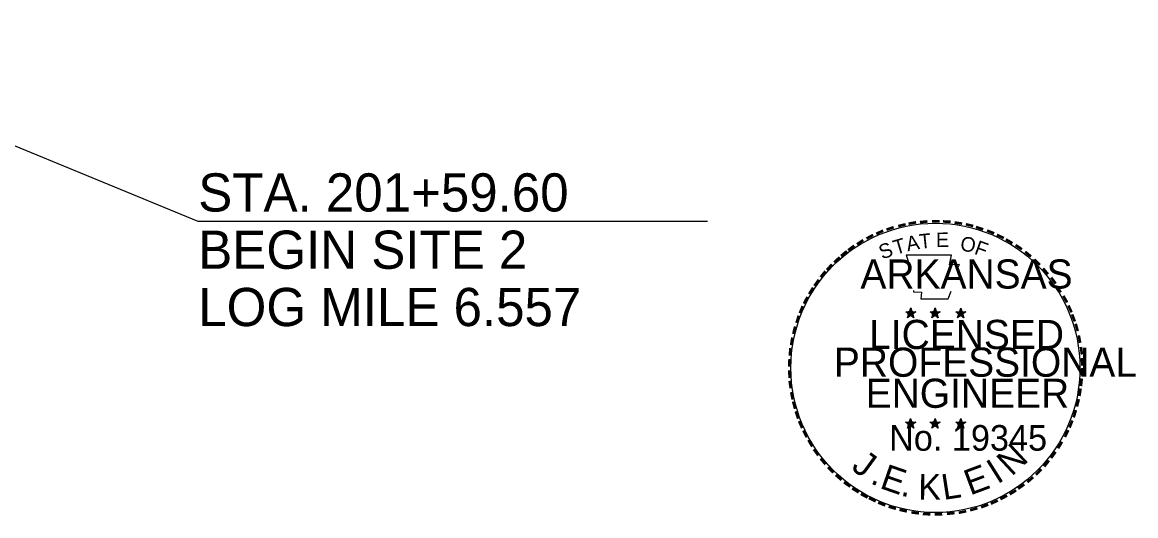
# Model space of a CAD drawing. Extents: x 1334737.7 to 1334827.2, y 402732.3 to 402753.5.
# Drawn here: x 1334760.94 to 1334768.64, y 402733.45 to 402736.86 of the extents above; entities that cross this region are included whole.
import ezdxf

# ---------------------------------------------------------------- set-up
doc = ezdxf.new("R2010")
doc.units = 0
doc.layers.add('Default', color=7, linetype='Continuous')
doc.layers.add('S_BASELINE_ANNOT', color=7, linetype='Continuous')

msp = doc.modelspace()

# ---------------------------------------------------------------- linework, layer by layer
at = {"layer": 'Default'}
for p, q in [((1334762.1527, 402735.4822), (1334753.3271, 402739.1037)), ((1334765.6746, 402735.4822), (1334762.1527, 402735.4822))]:
    msp.add_line(p, q, dxfattribs=at)
at = {"layer": 'S_BASELINE_ANNOT'}
for p, q in [((1334767.0814, 402734.8838), (1334767.0773, 402734.8578)), ((1334767.0814, 402734.8464), (1334767.0814, 402734.8838)), ((1334767.0814, 402734.8838), (1334767.0866, 402734.8589)), ((1334767.2504, 402734.8838), (1334767.2463, 402734.8578)), ((1334767.2504, 402734.8464), (1334767.2504, 402734.8838)), ((1334767.2504, 402734.8838), (1334767.2546, 402734.8589)), ((1334767.4277, 402734.8817), (1334767.4236, 402734.8568)), ((1334767.4277, 402734.8454), (1334767.4277, 402734.8817)), ((1334767.4277, 402734.8817), (1334767.4319, 402734.8568)), ((1334767.0462, 402734.8578), (1334767.0814, 402734.8464)), ((1334767.0462, 402734.8578), (1334767.0721, 402734.8537)), ((1334767.0462, 402734.8578), (1334767.07, 402734.8454)), ((1334767.0596, 402734.8164), (1334767.0814, 402734.8464)), ((1334767.0596, 402734.8164), (1334767.0721, 402734.8413)), ((1334767.0596, 402734.8164), (1334767.0804, 402734.8381)), ((1334767.1032, 402734.8164), (1334767.0804, 402734.8381)), ((1334767.1156, 402734.8578), (1334767.0814, 402734.8464)), ((1334767.1032, 402734.8164), (1334767.0814, 402734.8464)), ((1334767.1156, 402734.8578), (1334767.0876, 402734.8527)), ((1334767.1032, 402734.8164), (1334767.0887, 402734.8454)), ((1334767.1156, 402734.8578), (1334767.0959, 402734.8475)), ((1334767.2152, 402734.8578), (1334767.2504, 402734.8464)), ((1334767.2152, 402734.8578), (1334767.24, 402734.8537)), ((1334767.2152, 402734.8578), (1334767.238, 402734.8454)), ((1334767.2276, 402734.8164), (1334767.2504, 402734.8464)), ((1334767.2276, 402734.8164), (1334767.2411, 402734.8413)), ((1334767.2276, 402734.8164), (1334767.2494, 402734.8381)), ((1334767.2712, 402734.8164), (1334767.2494, 402734.8381)), ((1334767.2846, 402734.8578), (1334767.2504, 402734.8464)), ((1334767.2712, 402734.8164), (1334767.2504, 402734.8464)), ((1334767.2846, 402734.8578), (1334767.2556, 402734.8527)), ((1334767.2712, 402734.8164), (1334767.2566, 402734.8454)), ((1334767.2846, 402734.8578), (1334767.2639, 402734.8475)), ((1334767.3925, 402734.8568), (1334767.4277, 402734.8454)), ((1334767.3925, 402734.8568), (1334767.4173, 402734.8516)), ((1334767.3925, 402734.8568), (1334767.4163, 402734.8444)), ((1334767.4049, 402734.8153), (1334767.4277, 402734.8454)), ((1334767.4049, 402734.8153), (1334767.4184, 402734.8402)), ((1334767.4049, 402734.8153), (1334767.4277, 402734.8371)), ((1334767.463, 402734.8568), (1334767.4277, 402734.8454)), ((1334767.4485, 402734.8153), (1334767.4277, 402734.8454)), ((1334767.4485, 402734.8153), (1334767.4277, 402734.8371)), ((1334767.463, 402734.8568), (1334767.4329, 402734.8516)), ((1334767.4485, 402734.8153), (1334767.435, 402734.8444)), ((1334767.463, 402734.8568), (1334767.4412, 402734.8464)), ((1334767.0804, 402734.1196), (1334767.0762, 402734.0947)), ((1334767.0804, 402734.0833), (1334767.0804, 402734.1196)), ((1334767.0804, 402734.1196), (1334767.0856, 402734.0947)), ((1334767.2494, 402734.1196), (1334767.2452, 402734.0947)), ((1334767.2494, 402734.0833), (1334767.2494, 402734.1196)), ((1334767.2494, 402734.1196), (1334767.2535, 402734.0947)), ((1334767.4277, 402734.1186), (1334767.4236, 402734.0937)), ((1334767.4277, 402734.0823), (1334767.4277, 402734.1186)), ((1334767.4277, 402734.1186), (1334767.4319, 402734.0937)), ((1334767.0451, 402734.0947), (1334767.0804, 402734.0833)), ((1334767.0451, 402734.0947), (1334767.0721, 402734.0895)), ((1334767.0451, 402734.0947), (1334767.07, 402734.0823)), ((1334767.0596, 402734.0533), (1334767.0804, 402734.0833)), ((1334767.0596, 402734.0533), (1334767.0721, 402734.0781)), ((1334767.0596, 402734.0533), (1334767.0804, 402734.0761)), ((1334767.1156, 402734.0947), (1334767.0804, 402734.0833)), ((1334767.1032, 402734.0533), (1334767.0804, 402734.0833)), ((1334767.1032, 402734.0533), (1334767.0804, 402734.075)), ((1334767.1156, 402734.0947), (1334767.0866, 402734.0895)), ((1334767.1032, 402734.0533), (1334767.0887, 402734.0823)), ((1334767.1156, 402734.0947), (1334767.0959, 402734.0844)), ((1334767.2141, 402734.0947), (1334767.2494, 402734.0833)), ((1334767.2141, 402734.0947), (1334767.24, 402734.0895)), ((1334767.2141, 402734.0947), (1334767.238, 402734.0823)), ((1334767.2276, 402734.0533), (1334767.2494, 402734.0833)), ((1334767.2276, 402734.0533), (1334767.24, 402734.0781)), ((1334767.2276, 402734.0533), (1334767.2494, 402734.0761)), ((1334767.2846, 402734.0947), (1334767.2494, 402734.0833)), ((1334767.2701, 402734.0533), (1334767.2494, 402734.0833)), ((1334767.2701, 402734.0533), (1334767.2494, 402734.075)), ((1334767.2846, 402734.0947), (1334767.2546, 402734.0895)), ((1334767.2701, 402734.0533), (1334767.2566, 402734.0823)), ((1334767.2846, 402734.0947), (1334767.2629, 402734.0844)), ((1334767.3925, 402734.0937), (1334767.4277, 402734.0823)), ((1334767.3925, 402734.0937), (1334767.4173, 402734.0885)), ((1334767.3925, 402734.0937), (1334767.4163, 402734.0813)), ((1334767.4049, 402734.0522), (1334767.4277, 402734.0823)), ((1334767.4049, 402734.0522), (1334767.4184, 402734.0771)), ((1334767.4049, 402734.0522), (1334767.4277, 402734.075)), ((1334767.463, 402734.0937), (1334767.4277, 402734.0823)), ((1334767.4485, 402734.0522), (1334767.4277, 402734.0823)), ((1334767.4485, 402734.0522), (1334767.4277, 402734.074)), ((1334767.463, 402734.0937), (1334767.4329, 402734.0885)), ((1334767.4485, 402734.0522), (1334767.4339, 402734.0813)), ((1334767.463, 402734.0937), (1334767.4412, 402734.0833))]:
    msp.add_line(p, q, dxfattribs=at)
for points in [[(1334767.0503, 402735.2487), (1334767.0773, 402735.1647)], [(1334767.4039, 402735.1565), (1334767.4184, 402735.1844), (1334767.35, 402735.1824), (1334767.3634, 402735.2487), (1334767.0503, 402735.2487)], [(1334767.1001, 402735.0051), (1334767.1001, 402734.9957), (1334767.1561, 402734.9937), (1334767.1509, 402734.946), (1334767.3396, 402734.946), (1334767.3603, 402734.9999)], [(1334767.0814, 402734.8838), (1334767.1032, 402734.8164), (1334767.0462, 402734.8578), (1334767.1156, 402734.8578), (1334767.0596, 402734.8164), (1334767.0814, 402734.8838)], [(1334767.2504, 402734.8838), (1334767.2712, 402734.8164), (1334767.2152, 402734.8578), (1334767.2846, 402734.8578), (1334767.2276, 402734.8164), (1334767.2504, 402734.8838)], [(1334767.4277, 402734.8817), (1334767.4485, 402734.8153), (1334767.3925, 402734.8568), (1334767.463, 402734.8568), (1334767.4049, 402734.8153), (1334767.4277, 402734.8817)], [(1334767.0804, 402734.1196), (1334767.1032, 402734.0533), (1334767.0451, 402734.0947), (1334767.1156, 402734.0947), (1334767.0596, 402734.0533), (1334767.0804, 402734.1196)], [(1334767.2494, 402734.1196), (1334767.2701, 402734.0533), (1334767.2141, 402734.0947), (1334767.2846, 402734.0947), (1334767.2276, 402734.0533), (1334767.2494, 402734.1196)], [(1334767.4277, 402734.1186), (1334767.4485, 402734.0522), (1334767.3925, 402734.0937), (1334767.463, 402734.0937), (1334767.4049, 402734.0522), (1334767.4277, 402734.1186)]]:
    msp.add_lwpolyline(points, dxfattribs=at)
for centre, radius in [((1334767.2518, 402734.4692), 1), ((1334767.0805, 402734.8463), 0.0174), ((1334767.0805, 402734.8463), 0.0146), ((1334767.0805, 402734.8463), 0.0117), ((1334767.0805, 402734.8463), 0.00999), ((1334767.0805, 402734.8463), 0.00753), ((1334767.0805, 402734.8463), 0.00499), ((1334767.0805, 402734.8463), 0.00299), ((1334767.2488, 402734.8463), 0.0174), ((1334767.2488, 402734.8463), 0.0146), ((1334767.2488, 402734.8463), 0.0117), ((1334767.2488, 402734.8463), 0.00999), ((1334767.2488, 402734.8463), 0.00753), ((1334767.2488, 402734.8463), 0.00499), ((1334767.2488, 402734.8463), 0.00299), ((1334767.4266, 402734.8451), 0.0174), ((1334767.4266, 402734.8451), 0.0146), ((1334767.4266, 402734.8451), 0.0117), ((1334767.4266, 402734.8451), 0.00999), ((1334767.4266, 402734.8451), 0.00753), ((1334767.4266, 402734.8451), 0.00499), ((1334767.4266, 402734.8451), 0.00299), ((1334767.0801, 402734.0831), 0.0174), ((1334767.0801, 402734.0831), 0.0146), ((1334767.0801, 402734.0831), 0.0117), ((1334767.0801, 402734.0831), 0.00999), ((1334767.0801, 402734.0831), 0.00753), ((1334767.0801, 402734.0831), 0.00499), ((1334767.0801, 402734.0831), 0.00299), ((1334767.2483, 402734.0831), 0.0174), ((1334767.2483, 402734.0831), 0.0146), ((1334767.2483, 402734.0831), 0.0117), ((1334767.2483, 402734.0831), 0.00999), ((1334767.2483, 402734.0831), 0.00753), ((1334767.2483, 402734.0831), 0.00499), ((1334767.2483, 402734.0831), 0.00299), ((1334767.4264, 402734.0821), 0.0174), ((1334767.4264, 402734.0821), 0.0146), ((1334767.4264, 402734.0821), 0.0117), ((1334767.4264, 402734.0821), 0.00999), ((1334767.4264, 402734.0821), 0.00753), ((1334767.4264, 402734.0821), 0.00499), ((1334767.4264, 402734.0821), 0.00299)]:
    msp.add_circle(centre, radius, dxfattribs=at)

# ---------------------------------------------------------------- texts
at = {"layer": 'Default'}
for s, p in [('STA. 201+59.60', (1334762.1527, 402735.5502)), ('BEGIN SITE 2', (1334762.1527, 402735.1542)), ('LOG MILE 6.557', (1334762.1527, 402734.7581))]:
    msp.add_text(s, height=0.264042, dxfattribs=at).set_placement(p)
at = {"layer": 'S_BASELINE_ANNOT'}
for s, height, rotation, p in [('-', 0.1612, 5.89682, (1334767.1415, 402735.4136)), ('-', 0.1612, 0.18623, (1334767.2193, 402735.4208)), ('-', 0.1612, 357.74304, (1334767.2919, 402735.4198)), ('-', 0.1612, 24.30721, (1334766.8595, 402735.3358)), ('-', 0.1612, 19.17608, (1334766.9249, 402735.3628)), ('-', 0.1612, 13.63015, (1334767.0005, 402735.3866)), ('-', 0.1612, 10.21935, (1334767.0679, 402735.4032)), ('-', 0.1612, 352.16173, (1334767.3665, 402735.4136)), ('-', 0.1612, 347.20489, (1334767.4391, 402735.4032)), ('-', 0.1612, 342.3362, (1334767.5044, 402735.3866)), ('-', 0.1612, 337.85509, (1334767.577, 402735.3649)), ('-', 0.1612, 34.06357, (1334766.7361, 402735.2664)), ('-', 0.1612, 28.79182, (1334766.7963, 402735.3037)), ('T', 0.1008, 16.4036, (1334766.9767, 402735.2498)), ('A', 0.1008, 11.21318, (1334767.0596, 402735.2747)), ('T', 0.1008, 6.02276, (1334767.1447, 402735.2923)), ('E', 0.1008, 0.83234, (1334767.2566, 402735.3037)), ('O', 0.1008, 350.4515, (1334767.4184, 402735.2819)), ('F', 0.1008, 340.07066, (1334767.5148, 402735.2591)), ('-', 0.1612, 334.12109, (1334767.6413, 402735.3379)), ('-', 0.1612, 329.64089, (1334767.6994, 402735.3089)), ('-', 0.1612, 38.95066, (1334766.6304, 402735.1886)), ('-', 0.1612, 36.23174, (1334766.677, 402735.227)), ('S', 0.1008, 21.59401, (1334766.8844, 402735.2166)), ('-', 0.1612, 325.86266, (1334767.7637, 402735.2726)), ('-', 0.1612, 320.52971, (1334767.8259, 402735.2301)), ('-', 0.1612, 48.42305, (1334766.5412, 402735.0974)), ('-', 0.1612, 42.96224, (1334766.5868, 402735.1461)), ('-', 0.1612, 315.57859, (1334767.886, 402735.1803)), ('-', 0.1612, 50.61417, (1334766.4997, 402735.0497)), ('-', 0.1612, 309.87973, (1334767.943, 402735.1243)), ('-', 0.1612, 58.07063, (1334766.4261, 402734.9387)), ('-', 0.1612, 54.23247, (1334766.4593, 402734.9916)), ('-', 0.1612, 306.65218, (1334767.9969, 402735.0642)), ('-', 0.1411, 303.67529, (1334768.0446, 402735.0071)), ('-', 0.1612, 62.87135, (1334766.394, 402734.8765)), ('-', 0.1612, 299.66835, (1334768.0778, 402734.9449)), ('-', 0.1612, 67.77427, (1334766.3681, 402734.8153)), ('-', 0.1612, 294.66279, (1334768.111, 402734.8838)), ('-', 0.1612, 72.39447, (1334766.3473, 402734.7521)), ('-', 0.1612, 290.57283, (1334768.1359, 402734.8267)), ('-', 0.1612, 75.46096, (1334766.3266, 402734.6795)), ('-', 0.1612, 285.12326, (1334768.1597, 402734.7676)), ('-', 0.1612, 81.20126, (1334766.3142, 402734.608)), ('-', 0.1612, 280.54934, (1334768.1805, 402734.692)), ('-', 0.1612, 85.18634, (1334766.3059, 402734.5385)), ('-', 0.1612, 276.59616, (1334768.196, 402734.6163)), ('-', 0.1612, 89.06224, (1334766.3038, 402734.468)), ('-', 0.1612, 274.33011, (1334768.2022, 402734.5426)), ('-', 0.1612, 94.19588, (1334766.3069, 402734.3944)), ('-', 0.1612, 269.94067, (1334768.2053, 402734.4784)), ('-', 0.1612, 98.94793, (1334766.3142, 402734.328)), ('-', 0.1612, 263.5172, (1334768.2033, 402734.412)), ('-', 0.1612, 101.71495, (1334766.3276, 402734.2534)), ('-', 0.1612, 260.99529, (1334768.196, 402734.3456)), ('-', 0.1612, 105.45785, (1334766.3442, 402734.1932)), ('-', 0.1612, 255.7626, (1334768.1856, 402734.2772)), ('-', 0.1612, 109.08742, (1334766.365, 402734.13)), ('-', 0.1612, 114.06432, (1334766.3909, 402734.0698)), ('-', 0.1612, 247.88866, (1334768.1452, 402734.1372)), ('-', 0.1612, 252.86809, (1334768.167, 402734.2046)), ('-', 0.1612, 115.72885, (1334766.422, 402734.0076)), ('-', 0.1612, 244.61971, (1334768.1182, 402734.074)), ('-', 0.1612, 120.44712, (1334766.4583, 402733.9485)), ('-', 0.1612, 239.07125, (1334768.0788, 402733.9983)), ('-', 0.1612, 125.89344, (1334766.4977, 402733.8925)), ('J', 0.1771, 323.9056, (1334766.6631, 402733.7704)), ('N', 0.1771, 42.9205, (1334767.7792, 402733.7148)), ('-', 0.1612, 233.84524, (1334768.0384, 402733.933)), ('-', 0.1612, 130.71812, (1334766.5454, 402733.8355)), ('E', 0.1771, 340.88815, (1334766.8599, 402733.6403)), ('E', 0.1771, 20.50421, (1334767.4921, 402733.5859)), ('I', 0.1771, 32.2382, (1334767.6809, 402733.6621)), ('-', 0.1612, 231.25377, (1334767.9949, 402733.8749)), ('-', 0.1612, 134.22381, (1334766.5972, 402733.7816)), ('-', 0.1612, 138.93382, (1334766.6501, 402733.735)), ('K', 0.1771, 359.31489, (1334767.1322, 402733.559)), ('L', 0.1771, 8.77022, (1334767.3082, 402733.5556)), ('-', 0.1612, 221.08509, (1334767.8943, 402733.7671)), ('-', 0.1612, 225.76533, (1334767.9461, 402733.8189)), ('-', 0.1612, 144.64634, (1334766.7061, 402733.6935)), ('-', 0.1612, 148.08978, (1334766.7621, 402733.6562)), ('.', 0.1771, 336.34072, (1334766.7954, 402733.674)), ('-', 0.1612, 215.73633, (1334767.8383, 402733.7204)), ('-', 0.1612, 151.57039, (1334766.8201, 402733.623)), ('-', 0.1612, 154.60019, (1334766.874, 402733.5991)), ('.', 0.1771, 350.69404, (1334767.0068, 402733.5856)), ('-', 0.1612, 207.35684, (1334767.7284, 402733.6458)), ('-', 0.1612, 212.24909, (1334767.7854, 402733.681)), ('-', 0.1612, 158.56121, (1334766.9363, 402733.5732)), ('-', 0.1612, 162.79826, (1334767.0057, 402733.5514)), ('-', 0.1612, 167.55551, (1334767.0773, 402733.5359)), ('-', 0.1612, 191.28576, (1334767.4619, 402733.5411)), ('-', 0.1612, 195.47429, (1334767.5355, 402733.5618)), ('-', 0.1612, 200.71842, (1334767.604, 402733.5856)), ('-', 0.1612, 204.25161, (1334767.6662, 402733.6126)), ('-', 0.1612, 173.11546, (1334767.155, 402733.5245)), ('-', 0.1612, 176.51827, (1334767.2307, 402733.5183)), ('-', 0.1612, 181.59176, (1334767.3064, 402733.5203)), ('-', 0.1612, 185.81666, (1334767.3873, 402733.5286))]:
    msp.add_text(s, height=height, rotation=rotation, dxfattribs=at).set_placement(p)
for s, height, p in [('ARKANSAS', 0.20156, (1334766.733, 402735.0175)), ('LICENSED', 0.20156, (1334766.7932, 402734.5997)), ('PROFESSIONAL', 0.201561, (1334766.5495, 402734.4079)), ('ENGINEER', 0.20156, (1334766.7693, 402734.1932)), ('No. 19345', 0.17707, (1334766.9315, 402733.8967))]:
    msp.add_text(s, height=height, dxfattribs=at).set_placement(p)

doc.saveas('drawing.dxf')
